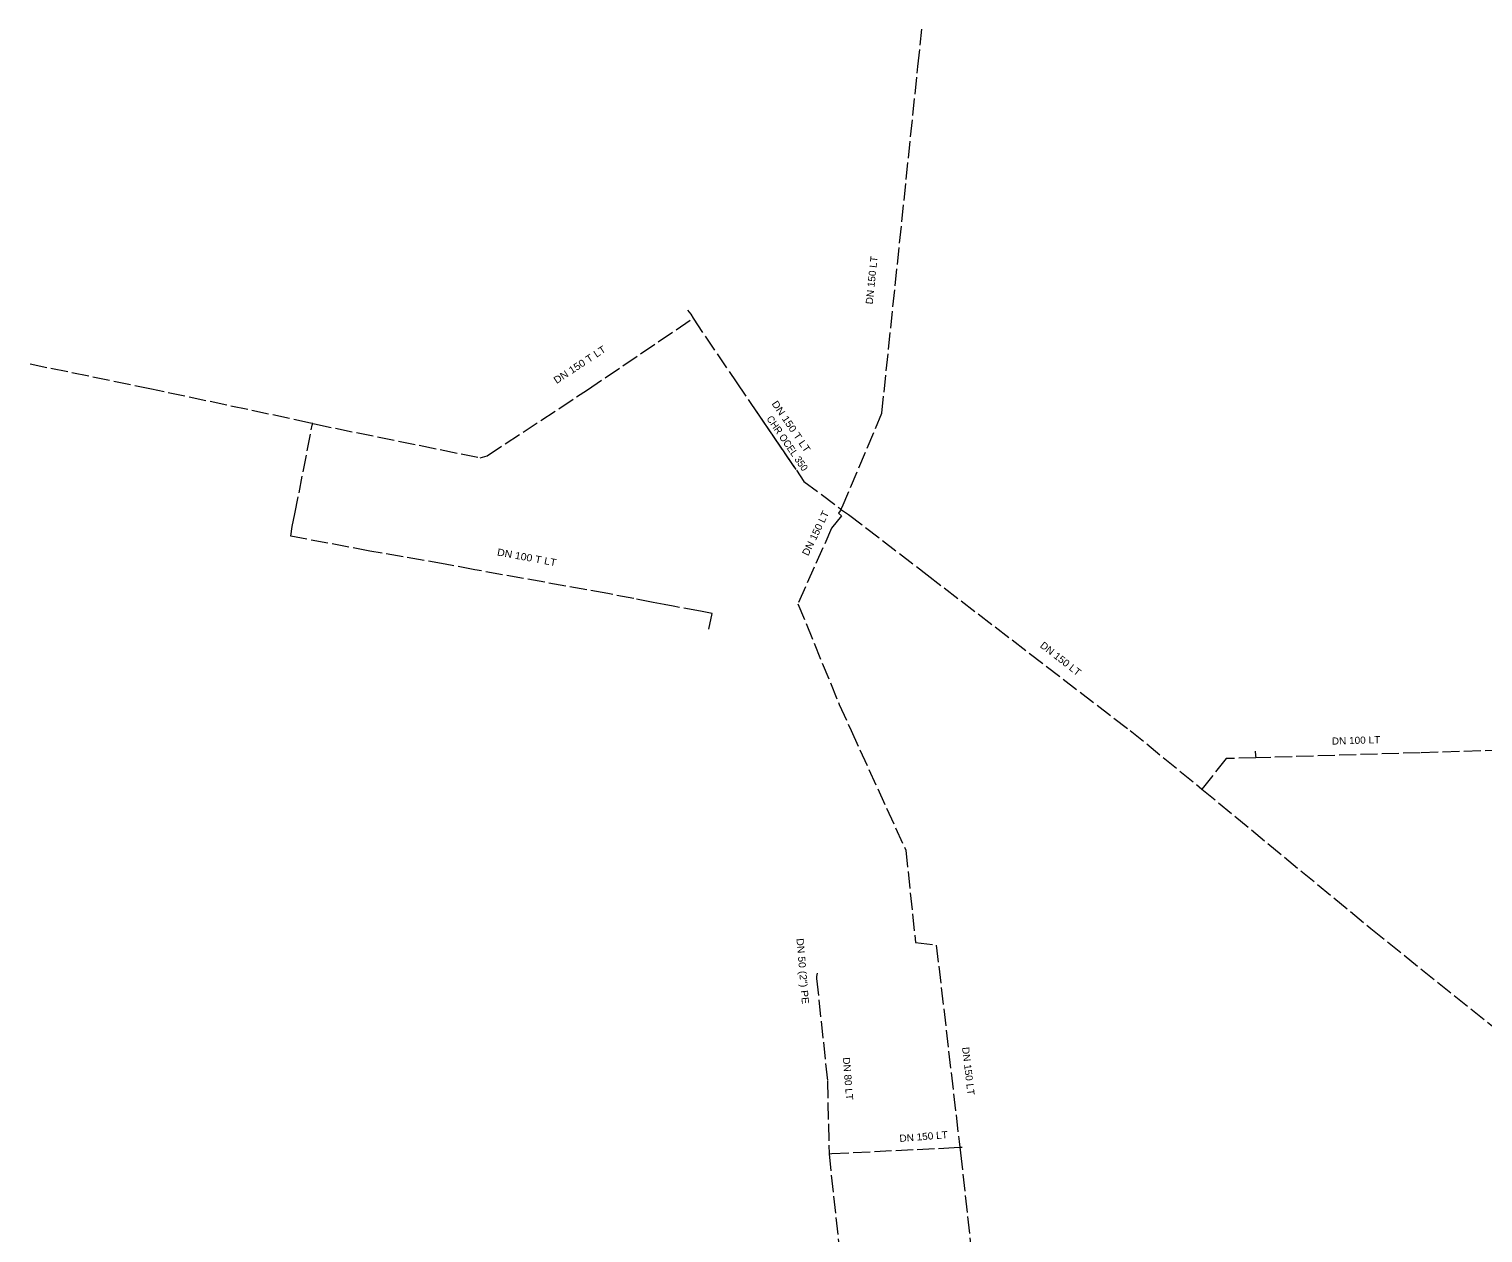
# Model space of a CAD drawing. Extents: x -642285 to -641979, y -1041680 to -1041425.
# Drawn here: x -642284.6 to -642131.6, y -1041552.9 to -1041426.2 of the extents above; entities that cross this region are included whole.
import ezdxf

# ---------------------------------------------------------------- set-up
doc = ezdxf.new("R2010")
doc.units = 0
doc.header["$LTSCALE"] = 0.3
doc.linetypes.add('LONG_DASHED', pattern=[7.5, 6, -1.5])
doc.layers.add('16', color=7, linetype='Continuous')
doc.layers.add('20', color=7, linetype='Continuous')
doc.layers.add('25', color=7, linetype='Continuous', lineweight=13)
doc.layers.add('35', color=7, linetype='LONG_DASHED', lineweight=13)

msp = doc.modelspace()

# ---------------------------------------------------------------- linework, layer by layer
at = {"layer": '25'}
msp.add_line((-642208.385, -1041465.94), (-642203.875, -1041472.55), dxfattribs=at)
at = {"layer": '35'}
for p, q in [((-642191.028, -1041430.132), (-642190.615, -1041426.195)), ((-642215.29, -1041455.76), (-642214.92, -1041456.2)), ((-642214.92, -1041456.2), (-642214.69, -1041456.63)), ((-642254.706, -1041467.707), (-642254.95, -1041467.65)), ((-642254.706, -1041467.707), (-642254.52, -1041467.75)), ((-642199.31, -1041476.58), (-642199.13, -1041476.75)), ((-642199.13, -1041476.75), (-642199, -1041476.52)), ((-642256.89, -1041478.53), (-642256.58, -1041477.2)), ((-642199.13, -1041476.75), (-642199.23, -1041476.88)), ((-642199.13, -1041476.75), (-642198.98, -1041476.84)), ((-642213.05, -1041489.33), (-642212.67, -1041487.71)), ((-642155.56, -1041502.18), (-642155.5, -1041502.64)), ((-642155.5, -1041502.64), (-642155.482, -1041502.889)), ((-642138.174, -1041502.346), (-642155.482, -1041502.889)), ((-642104.81, -1041501.3), (-642138.174, -1041502.346)), ((-642160.993, -1041505.972), (-642161.148, -1041506.168)), ((-642201.65, -1041525.55), (-642201.72, -1041525.89)), ((-642201.72, -1041525.89), (-642201.703, -1041526.103)), ((-642200.09, -1041544.52), (-642187.221, -1041543.899)), ((-642187.221, -1041543.899), (-642186.622, -1041543.851)), ((-642186.622, -1041543.851), (-642186.38, -1041543.832)), ((-642200.389, -1041544.544), (-642200.09, -1041544.52))]:
    msp.add_line(p, q, dxfattribs=at)
for points in [[(-642199, -1041476.52), (-642194.825, -1041466.627), (-642191.028, -1041430.132)], [(-642254.52, -1041467.75), (-642237.1, -1041471.3), (-642236.34, -1041471.09), (-642225.8, -1041464.15), (-642214.69, -1041456.63)], [(-642214.69, -1041456.63), (-642210.16, -1041463.33), (-642203.03, -1041473.79), (-642199.31, -1041476.58)], [(-642254.95, -1041467.65), (-642271.67, -1041464.08), (-642284.555, -1041461.45)], [(-642256.58, -1041477.2), (-642254.77, -1041467.89), (-642254.706, -1041467.707)], [(-642199.23, -1041476.88), (-642199.4, -1041477.13), (-642199.09, -1041477.41), (-642200.11, -1041478.72), (-642203.658, -1041486.662), (-642199.303, -1041497.284), (-642198.068, -1041500), (-642192.311, -1041512.597), (-642191.289, -1041522.31), (-642189.096, -1041522.582), (-642186.701, -1041543.256)], [(-642198.98, -1041476.84), (-642198.34, -1041477.27), (-642190.043, -1041483.634)], [(-642248.69, -1041481.13), (-642257.01, -1041479.56), (-642256.89, -1041478.53)], [(-642220.93, -1041486.13), (-642223.66, -1041485.6), (-642237.65, -1041483.09), (-642240.77, -1041482.51), (-642248.69, -1041481.13)], [(-642190.043, -1041483.634), (-642168.704, -1041500), (-642161.148, -1041506.168)], [(-642212.67, -1041487.71), (-642213.91, -1041487.46), (-642216.79, -1041486.92), (-642217.74, -1041486.74), (-642218.89, -1041486.53), (-642220.93, -1041486.13)], [(-642155.482, -1041502.889), (-642158.612, -1041502.956), (-642160.993, -1041505.972)], [(-642161.148, -1041506.168), (-642143.373, -1041520.845), (-642124.316, -1041536.132)], [(-642201.703, -1041526.103), (-642200.547, -1041536.893), (-642200.389, -1041544.544), (-642198.012, -1041566.281)], [(-642186.701, -1041543.256), (-642186.622, -1041543.851), (-642186.557, -1041544.447)], [(-642186.557, -1041544.447), (-642184.273, -1041564.886), (-642180.812, -1041593.793)]]:
    msp.add_lwpolyline(points, dxfattribs=at)

# ---------------------------------------------------------------- texts
at = {"layer": '16'}
for s, rotation, width, p in [('DN 150 LT', 84.06, 1.05, (-642195.794, -1041455.19)), ('DN 150 T LT', 33.363, 1.1, (-642229.051, -1041463.559)), ('DN 150 T LT', 304.28, 1.1, (-642206.459, -1041465.618)), ('DN 150 LT', 64.066, 1.05, (-642202.583, -1041481.694)), ('DN 100 T LT', 349.469, 1.1, (-642235.354, -1041481.57)), ('DN 150 LT', 322.009, 1.05, (-642178.253, -1041491.18)), ('DN 100 LT', 1.796, 1.05, (-642147.473, -1041501.496)), ('DN 50 (2") PE', 274.884, 1.1, (-642203.819, -1041521.899)), ('DN 80 LT', 274.516, 1.05, (-642198.938, -1041534.419)), ('DN 150 LT', 276.636, 1.05, (-642186.393, -1041533.356)), ('DN 150 LT', 4.602, 1.05, (-642192.946, -1041543.304))]:
    msp.add_text(s, height=0.75, rotation=rotation, dxfattribs=dict(at, width=width)).set_placement(p)
at = {"layer": '20', "width": 0.95}
msp.add_text('CHR OCEL 350', height=0.75, rotation=304.472, dxfattribs=at).set_placement((-642207, -1041467.2))

doc.saveas('drawing.dxf')
